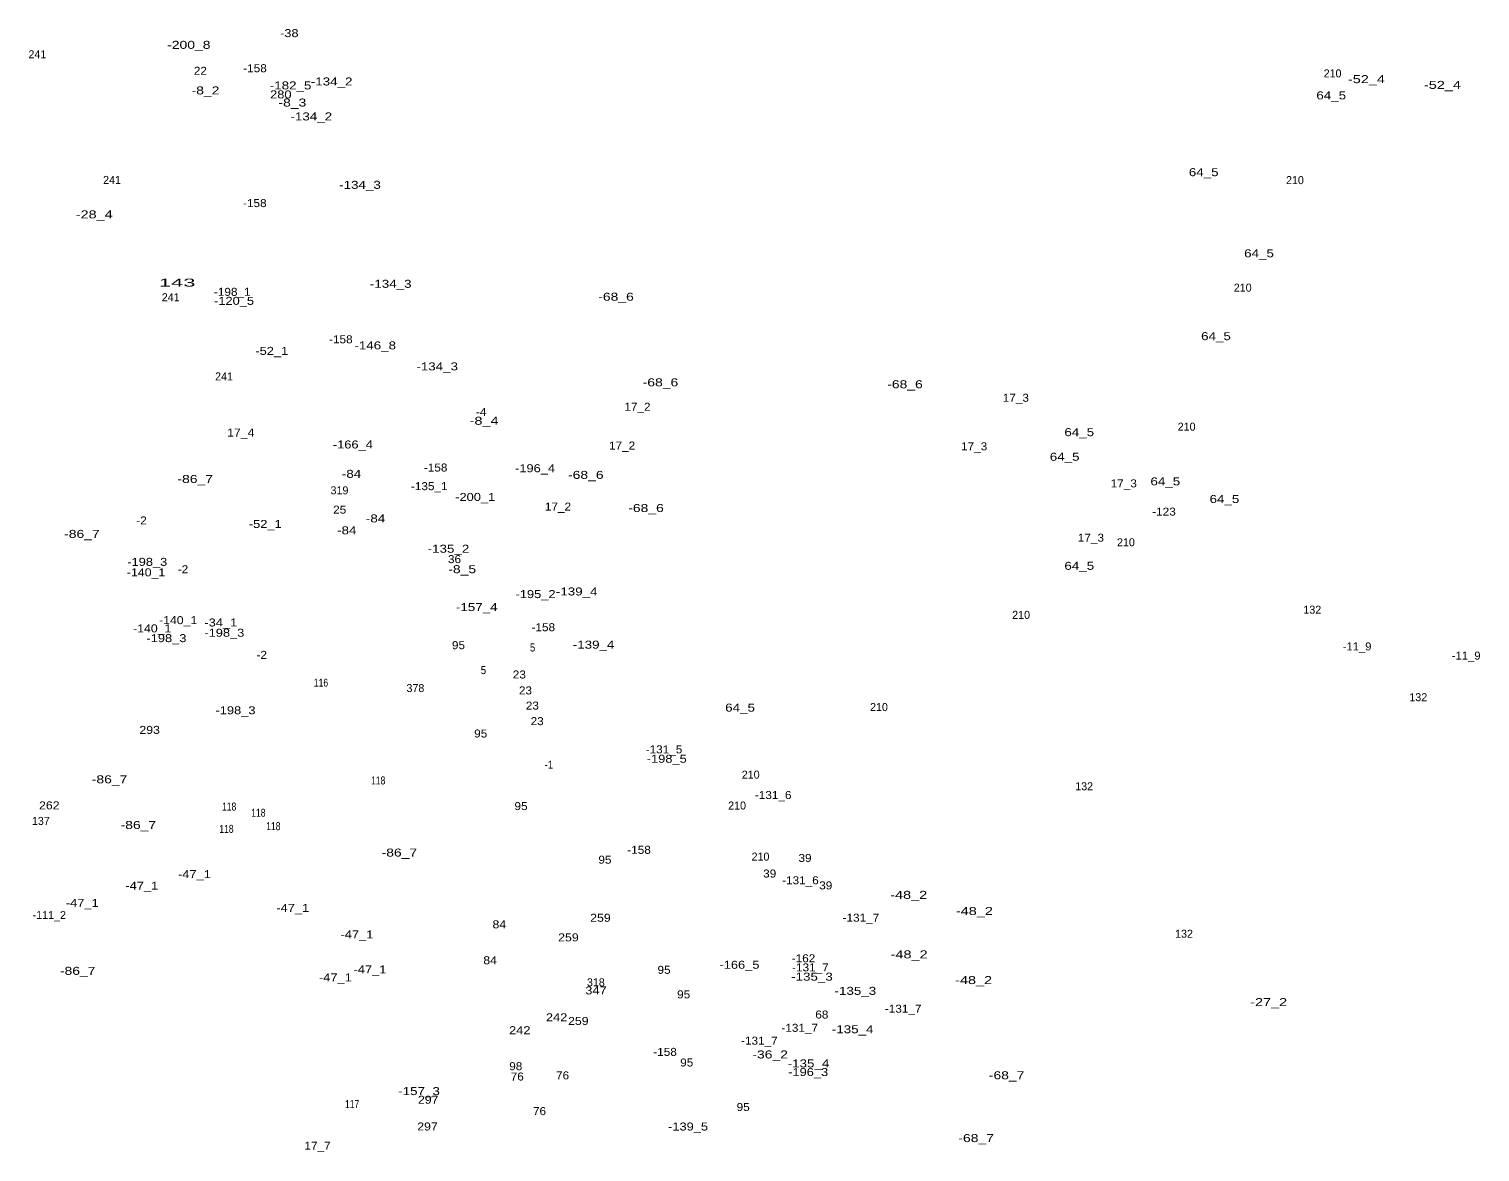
# Model space of a CAD drawing. Extents: x -662996 to -659766, y -998554 to -993949.
# Drawn here: x -661498 to -660773, y -996841 to -996279 of the extents above; entities that cross this region are included whole.
import ezdxf
from ezdxf.enums import TextEntityAlignment as Align

# ---------------------------------------------------------------- set-up
doc = ezdxf.new("R2010")
doc.units = 0
doc.header["$LTSCALE"] = 1.6
doc.layers.add('24', color=7, linetype='Continuous')

msp = doc.modelspace()

# ---------------------------------------------------------------- texts
at = {"layer": '24'}
for s, width, p in [('-38', 1.2, (-661368.01, -996282.99)), ('-200_8', 1.3, (-661418.24, -996288.85)), ('22', 1.1, (-661412.48, -996301.82)), ('-158', 1.1, (-661385.15, -996300.54)), ('-182_5', 1.25, (-661367.37, -996309.15)), ('-134_2', 1.25, (-661346.84, -996307.18)), ('-52_4', 1.35, (-660829.52, -996306.02)), ('-52_4', 1.35, (-660791.51, -996308.89)), ('-8_2', 1.3, (-661409.91, -996311.66)), ('280', 1.2, (-661372.25, -996313.65)), ('64_5', 1.25, (-660847.13, -996314.13)), ('-8_3', 1.3, (-661366.48, -996317.72)), ('-134_2', 1.25, (-661357.01, -996324.66)), ('64_5', 1.25, (-660910.87, -996352.55)), ('-134_3', 1.25, (-661332.669, -996358.88)), ('-158', 1.1, (-661385.25, -996368.02)), ('-28_4', 1.35, (-661465.54, -996373.66)), ('64_5', 1.25, (-660883.22, -996393.13)), ('143', 2.05, (-661424.073, -996407.79)), ('-134_3', 1.25, (-661317.309, -996408.39)), ('-198_1', 1.1, (-661396.53, -996412.4)), ('-120_5', 1.2, (-661395.63, -996416.91)), ('-68_6', 1.3, (-661204.67, -996414.86)), ('-158', 1.1, (-661342.24, -996436.14)), ('-146_8', 1.25, (-661325.06, -996439.19)), ('64_5', 1.25, (-660904.73, -996434.58)), ('-52_1', 1.2, (-661376.77, -996441.94)), ('-134_3', 1.25, (-661294.079, -996449.69)), ('-68_6', 1.3, (-661182.45, -996457.68)), ('-68_6', 1.3, (-661060.2, -996458.63)), ('17_3', 1.1, (-661004.799, -996465.38)), ('-4', 1.15, (-661272.07, -996472.44)), ('17_2', 1.1, (-661193.949, -996469.88)), ('17_4', 1.15, (-661392.27, -996482.77)), ('-8_4', 1.35, (-661270.63, -996476.9)), ('64_5', 1.25, (-660973.079, -996482.6)), ('-166_4', 1.2, (-661336.23, -996488.76)), ('17_2', 1.1, (-661201.63, -996489.28)), ('17_3', 1.1, (-661025.63, -996489.67)), ('64_5', 1.25, (-660980.38, -996494.9)), ('-84', 1.25, (-661336.89, -996503.45)), ('-158', 1.1, (-661294.851, -996500.28)), ('-196_4', 1.2, (-661245.15, -996500.64)), ('-68_6', 1.3, (-661219.77, -996503.97)), ('-86_7', 1.3, (-661415.051, -996506.02)), ('-135_1', 1.1, (-661298.049, -996509.6)), ('17_3', 1.1, (-660950.85, -996508.22)), ('64_5', 1.25, (-660930.069, -996507.19)), ('-200_1', 1.2, (-661275.07, -996515.01)), ('17_2', 1.1, (-661233.699, -996519.82)), ('64_5', 1.25, (-660900.51, -996516.02)), ('-2', 1.1, (-661441.88, -996526.76)), ('25', 1.1, (-661342.829, -996521.35)), ('-84', 1.25, (-661324.89, -996525.74)), ('-68_6', 1.3, (-661189.68, -996520.54)), ('-123', 1.1, (-660930.711, -996522.33)), ('-86_7', 1.3, (-661471.691, -996533.49)), ('-52_1', 1.2, (-661380.03, -996528.52)), ('-84', 1.25, (-661339.29, -996531.69)), ('-135_2', 1.25, (-661288.449, -996540.91)), ('17_3', 1.1, (-660967.26, -996535.38)), ('-198_3', 1.2, (-661439.02, -996547.47)), ('36', 1.1, (-661285.42, -996546.11)), ('-140_1', 1.15, (-661439.62, -996552.72)), ('-2', 1.1, (-661421.14, -996551.16)), ('-8_5', 1.3, (-661281.579, -996551.14)), ('64_5', 1.25, (-660973.079, -996549.45)), ('-195_2', 1.2, (-661244.9, -996563.6)), ('-139_4', 1.25, (-661224.34, -996562.29)), ('-157_4', 1.25, (-661274.29, -996570.09)), ('-140_1', 1.15, (-661423.579, -996576.62)), ('-34_1', 1.2, (-661402.25, -996577.8)), ('-140_1', 1.15, (-661436.54, -996580.75)), ('-198_3', 1.2, (-661429.431, -996585.63)), ('-198_3', 1.2, (-661400.49, -996582.93)), ('-158', 1.1, (-661241.02, -996580.17)), ('95', 1.1, (-661283.45, -996589.15)), ('5', 0.9, (-661246.38, -996590.3)), ('-139_4', 1.25, (-661215.89, -996588.89)), ('-11_9', 1.05, (-660834.201, -996589.77)), ('-2', 1.1, (-661381.78, -996593.99)), ('-11_9', 1.05, (-660779.671, -996594.38)), ('5', 0.9, (-661270.959, -996601.63)), ('23', 1.1, (-661253.02, -996603.81)), ('116', 0.8, (-661352.171, -996607.9)), ('23', 1.1, (-661249.949, -996611.78)), ('-198_3', 1.2, (-661394.9, -996621.72)), ('23', 1.1, (-661246.5, -996619.37)), ('64_5', 1.25, (-661142.66, -996620.39)), ('23', 1.1, (-661244.1, -996627.15)), ('293', 1.15, (-661437.82, -996631.52)), ('95', 1.1, (-661272.32, -996633.33)), ('-131_5', 1.1, (-661180.699, -996641.27)), ('-1', 0.9, (-661238.201, -996648.93)), ('-198_5', 1.2, (-661179.321, -996645.96)), ('-86_7', 1.3, (-661457.87, -996656.24)), ('118', 0.8, (-661323.57, -996656.82)), ('-131_6', 1.1, (-661126.111, -996664.1)), ('262', 1.15, (-661488, -996669.29)), ('118', 0.8, (-661398.07, -996669.88)), ('95', 1.1, (-661252.16, -996669.64)), ('-86_7', 1.3, (-661443.471, -996679.1)), ('118', 0.8, (-661383.48, -996672.95)), ('118', 0.8, (-661375.99, -996679.68)), ('118', 0.8, (-661399.42, -996681.02)), ('-86_7', 1.3, (-661312.981, -996692.89)), ('-158', 1.1, (-661193.171, -996691.51)), ('95', 1.1, (-661210.22, -996696.45)), ('39', 1.1, (-661110.19, -996695.59)), ('-47_1', 1.2, (-661415.43, -996703.69)), ('39', 1.1, (-661127.85, -996703.37)), ('-131_6', 1.1, (-661112.481, -996706.75)), ('-47_1', 1.2, (-661441.74, -996709.45)), ('39', 1.1, (-661099.82, -996709.32)), ('-48_2', 1.35, (-661058.35, -996714.04)), ('-47_1', 1.2, (-661471.5, -996718.09)), ('-47_1', 1.2, (-661366.28, -996720.59)), ('-48_2', 1.35, (-661025.51, -996722.11)), ('84', 1.15, (-661263, -996728.78)), ('259', 1.15, (-661212.47, -996725.5)), ('-131_7', 1.1, (-661082.24, -996725.46)), ('-47_1', 1.2, (-661334.21, -996733.84)), ('259', 1.15, (-661228.47, -996735.31)), ('-48_2', 1.35, (-661058.15, -996743.81)), ('-86_7', 1.3, (-661473.791, -996752.05)), ('-47_1', 1.2, (-661327.68, -996751.32)), ('84', 1.15, (-661267.61, -996746.74)), ('95', 1.1, (-661180.65, -996751.53)), ('-166_5', 1.2, (-661142.96, -996749.01)), ('-162', 1.1, (-661110.94, -996745.78)), ('-131_7', 1.1, (-661107.49, -996750.33)), ('-47_1', 1.2, (-661344.96, -996755.35)), ('-135_3', 1.25, (-661106.72, -996754.95)), ('-48_2', 1.35, (-661025.9, -996756.68)), ('347', 1.2, (-661214.69, -996761.84)), ('95', 1.1, (-661170.86, -996763.82)), ('-135_3', 1.25, (-661085.02, -996762.06)), ('68', 1.1, (-661101.78, -996773.91)), ('-131_7', 1.1, (-661061.12, -996770.98)), ('-27_2', 1.35, (-660878.4, -996767.67)), ('242', 1.2, (-661234.37, -996775.28)), ('259', 1.15, (-661223.52, -996777.12)), ('-131_7', 1.1, (-661112.841, -996780.55)), ('-135_4', 1.25, (-661086.37, -996781.26)), ('242', 1.2, (-661252.79, -996781.75)), ('-131_7', 1.1, (-661133.01, -996786.99)), ('-158', 1.1, (-661180.16, -996792.59)), ('-36_2', 1.3, (-661127.62, -996793.88)), ('98', 1.1, (-661254.79, -996799.76)), ('95', 1.1, (-661169.32, -996797.89)), ('-135_4', 1.25, (-661108.449, -996798.36)), ('-196_3', 1.2, (-661108.61, -996802.67)), ('76', 1.1, (-661254.06, -996804.92)), ('76', 1.1, (-661231.4, -996804.35)), ('-68_7', 1.3, (-661009.41, -996804.28)), ('-157_3', 1.25, (-661303.14, -996812.2)), ('297', 1.15, (-661298.58, -996816.52)), ('117', 0.8, (-661336.611, -996818.69)), ('76', 1.1, (-661242.92, -996822.21)), ('95', 1.1, (-661141.1, -996820.17)), ('297', 1.15, (-661298.92, -996829.9)), ('-139_5', 1.2, (-661168.66, -996829.92)), ('-68_7', 1.3, (-661024.65, -996835.71)), ('17_7', 1.1, (-661353.9, -996839.51))]:
    msp.add_text(s, height=4, dxfattribs=dict(at, width=width)).set_placement(p, align=Align.CENTER)
for s, p in [('241', (-661493.939, -996293.57)), ('210', (-660846.45, -996303.13)), ('241', (-661456.62, -996356.42)), ('210', (-660865.26, -996356.53)), ('210', (-660891.38, -996410.31)), ('241', (-661427.29, -996415.09)), ('241', (-661400.64, -996454.71)), ('210', (-660919.41, -996479.84)), ('319', (-661342.931, -996511.7)), ('210', (-660949.75, -996537.67)), ('210', (-661002.16, -996573.99)), ('132', (-660856.59, -996571.38)), ('378', (-661304.963, -996610.6)), ('210', (-661073.21, -996620.09)), ('132', (-660803.6, -996615.17)), ('210', (-661137.34, -996653.9)), ('132', (-660970.65, -996659.72)), ('210', (-661144.15, -996669.35)), ('137', (-661492.221, -996677.07)), ('210', (-661132.44, -996694.9)), ('-111_2', (-661488, -996724.13)), ('132', (-660920.72, -996733.48)), ('318', (-661214.76, -996757.78))]:
    msp.add_text(s, height=4, dxfattribs=at).set_placement(p, align=Align.CENTER)

doc.saveas('drawing.dxf')
